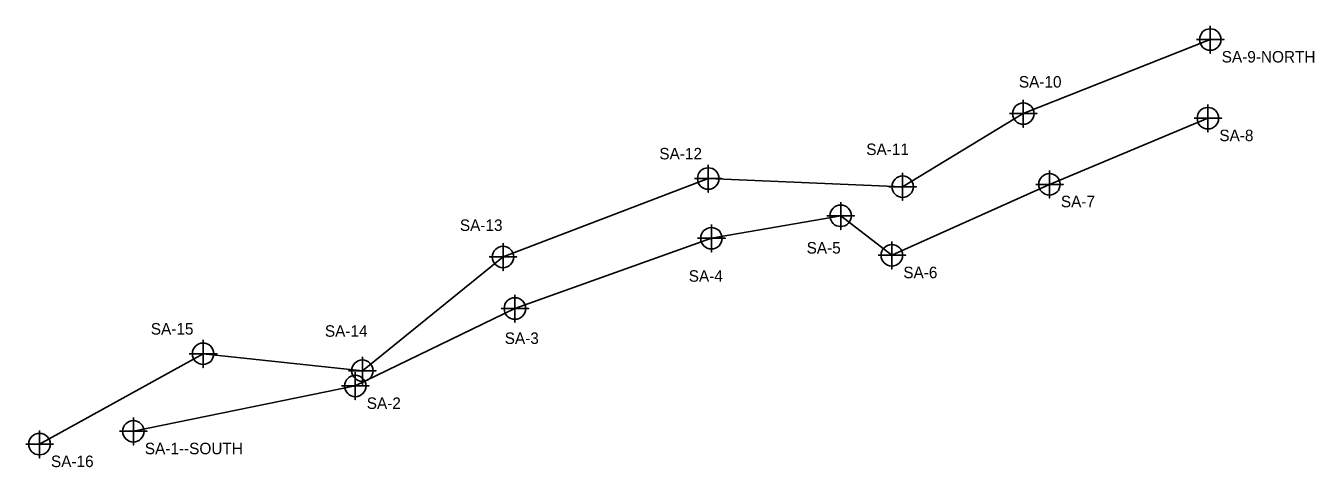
# Model space of a CAD drawing. Extents: x 1736087 to 1736368, y 700434 to 700530.
import ezdxf

# ---------------------------------------------------------------- set-up
doc = ezdxf.new("R2010")
doc.units = 0
for name, color, linetype in [('Exist Hydro Jurisdictional Stream or Body of Water NEU Mitigable', 7, 'Continuous'), ('Exist Hydro Jurisdictional Stream or Body of Water NEU Mitigable Cogo Comment', 7, 'Continuous'), ('Exist Hydro Jurisdictional Stream or Body of Water NEU Mitigable Cogo Point CELL', 7, 'Continuous')]:
    doc.layers.add(name, color=color, linetype=linetype)

msp = doc.modelspace()

# ---------------------------------------------------------------- linework, layer by layer
at = {"layer": 'Exist Hydro Jurisdictional Stream or Body of Water NEU Mitigable'}
for points in [[(1736345.23, 700527.22), (1736304.49, 700511.09), (1736278.18, 700495.16), (1736235.81, 700496.94), (1736191.09, 700479.85), (1736160.44, 700455.07), (1736125.72, 700458.76), (1736090.07, 700439.07)], [(1736110.53, 700441.87), (1736158.89, 700451.74), (1736193.67, 700468.62), (1736236.51, 700483.93), (1736264.68, 700488.82), (1736275.83, 700480.22), (1736310.18, 700495.67), (1736344.71, 700510.08)]]:
    msp.add_lwpolyline(points, dxfattribs=at)
at = {"layer": 'Exist Hydro Jurisdictional Stream or Body of Water NEU Mitigable Cogo Point CELL'}
for points in [[(1736345.23, 700530.22), (1736345.23, 700524.22), (1736345.23, 700527.22), (1736348.23, 700527.22), (1736342.23, 700527.22)], [(1736304.49, 700514.09), (1736304.49, 700508.09), (1736304.49, 700511.09), (1736307.49, 700511.09), (1736301.49, 700511.09)], [(1736344.71, 700513.08), (1736344.71, 700507.08), (1736344.71, 700510.08), (1736347.71, 700510.08), (1736341.71, 700510.08)], [(1736235.81, 700499.94), (1736235.81, 700493.94), (1736235.81, 700496.94), (1736238.81, 700496.94), (1736232.81, 700496.94)], [(1736278.18, 700498.16), (1736278.18, 700492.16), (1736278.18, 700495.16), (1736281.18, 700495.16), (1736275.18, 700495.16)], [(1736310.18, 700498.67), (1736310.18, 700492.67), (1736310.18, 700495.67), (1736313.18, 700495.67), (1736307.18, 700495.67)], [(1736264.68, 700491.82), (1736264.68, 700485.82), (1736264.68, 700488.82), (1736267.68, 700488.82), (1736261.68, 700488.82)], [(1736236.51, 700486.93), (1736236.51, 700480.93), (1736236.51, 700483.93), (1736239.51, 700483.93), (1736233.51, 700483.93)], [(1736191.09, 700482.85), (1736191.09, 700476.85), (1736191.09, 700479.85), (1736194.09, 700479.85), (1736188.09, 700479.85)], [(1736275.83, 700483.22), (1736275.83, 700477.22), (1736275.83, 700480.22), (1736278.83, 700480.22), (1736272.83, 700480.22)], [(1736193.67, 700471.62), (1736193.67, 700465.62), (1736193.67, 700468.62), (1736196.67, 700468.62), (1736190.67, 700468.62)], [(1736125.72, 700461.76), (1736125.72, 700455.76), (1736125.72, 700458.76), (1736128.72, 700458.76), (1736122.72, 700458.76)], [(1736160.44, 700458.07), (1736160.44, 700452.07), (1736160.44, 700455.07), (1736163.44, 700455.07), (1736157.44, 700455.07)], [(1736158.89, 700454.74), (1736158.89, 700448.74), (1736158.89, 700451.74), (1736161.89, 700451.74), (1736155.89, 700451.74)], [(1736110.53, 700444.87), (1736110.53, 700438.87), (1736110.53, 700441.87), (1736113.53, 700441.87), (1736107.53, 700441.87)], [(1736090.07, 700442.07), (1736090.07, 700436.07), (1736090.07, 700439.07), (1736093.07, 700439.07), (1736087.07, 700439.07)]]:
    msp.add_lwpolyline(points, dxfattribs=at)
for centre in [(1736345.23, 700527.22), (1736304.49, 700511.09), (1736344.71, 700510.08), (1736235.81, 700496.94), (1736278.18, 700495.16), (1736310.18, 700495.67), (1736264.68, 700488.82), (1736236.51, 700483.93), (1736191.09, 700479.85), (1736275.83, 700480.22), (1736193.67, 700468.62), (1736125.72, 700458.76), (1736160.44, 700455.07), (1736158.89, 700451.74), (1736110.53, 700441.87), (1736090.07, 700439.07)]:
    msp.add_circle(centre, 2.34, dxfattribs=at)

# ---------------------------------------------------------------- texts
at = {"layer": 'Exist Hydro Jurisdictional Stream or Body of Water NEU Mitigable Cogo Comment'}
for s, p in [('SA-9-NORTH', (1736347.73, 700522.22)), ('SA-10', (1736303.52, 700516.76)), ('SA-8', (1736347.21, 700505.08)), ('SA-11', (1736270.26, 700502.06)), ('SA-12', (1736225.16, 700501.11)), ('SA-7', (1736312.68, 700490.68)), ('SA-13', (1736181.69, 700485.52)), ('SA-5', (1736257.26, 700480.59)), ('SA-4', (1736231.57, 700474.46)), ('SA-6', (1736278.33, 700475.22)), ('SA-15', (1736114.33, 700462.94)), ('SA-14', (1736152.27, 700462.47)), ('SA-3', (1736191.46, 700460.9)), ('SA-2', (1736161.39, 700446.74)), ('SA-1--SOUTH', (1736113.03, 700436.87)), ('SA-16', (1736092.57, 700434.07))]:
    msp.add_text(s, height=2.5, dxfattribs=at).set_placement(p)

doc.saveas('drawing.dxf')
